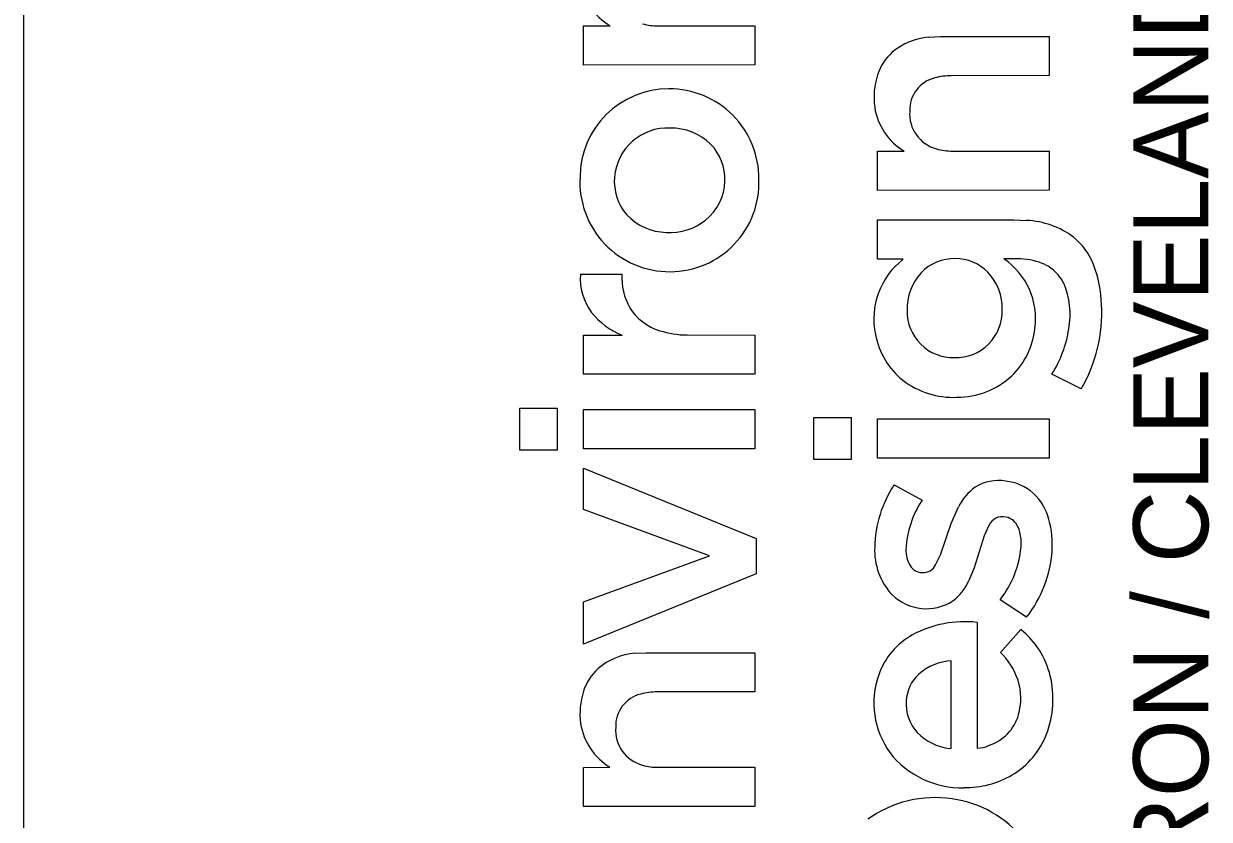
# Model space of a CAD drawing. Extents: x -0.2 to 34, y 0 to 22.
# Drawn here: x 32 to 32.901, y 2.778 to 3.382 of the extents above; entities that cross this region are included whole.
import ezdxf

# ---------------------------------------------------------------- set-up
doc = ezdxf.new("R2010")
doc.units = 0
doc.layers.add('SH_Border', color=7, linetype='Continuous')
doc.layers.add('SH_Cut_Line', color=7, linetype='Continuous')

msp = doc.modelspace()

# ---------------------------------------------------------------- linework, layer by layer
at = {"layer": 'SH_Border'}
for p, q in [((32.42542, 3.38066), (32.44552, 3.38071)), ((32.42542, 3.35086), (32.42542, 3.38066)), ((32.48222, 3.38071), (32.55569, 3.38071)), ((32.55569, 3.38071), (32.55571, 3.35096)), ((32.68784, 3.3722), (32.69634, 3.37266)), ((32.69634, 3.37266), (32.77916, 3.37266)), ((32.77916, 3.37266), (32.77917, 3.34287)), ((32.55571, 3.35096), (32.42542, 3.35086)), ((32.77917, 3.34287), (32.70485, 3.3428)), ((32.64888, 3.2855), (32.66897, 3.28555)), ((32.64888, 3.25569), (32.64888, 3.2855)), ((32.70568, 3.28555), (32.77915, 3.28555)), ((32.77915, 3.28555), (32.77917, 3.25579)), ((32.77917, 3.25579), (32.64888, 3.25569)), ((32.6489, 3.20336), (32.64889, 3.23322)), ((32.64889, 3.23322), (32.75236, 3.23322)), ((32.75236, 3.23322), (32.76191, 3.23285)), ((32.66836, 3.20336), (32.6489, 3.20336)), ((32.75763, 3.20356), (32.74487, 3.20361)), ((32.42299, 3.19193), (32.45454, 3.19193)), ((32.42542, 3.14577), (32.45473, 3.14579)), ((32.42542, 3.11593), (32.42542, 3.14577)), ((32.50413, 3.14581), (32.55571, 3.14573)), ((32.55571, 3.14573), (32.55565, 3.11593)), ((32.55565, 3.11593), (32.42542, 3.11593)), ((32.8036, 3.10491), (32.7812, 3.11598)), ((32.37705, 3.05818), (32.37705, 3.09026)), ((32.37705, 3.09026), (32.40543, 3.09026)), ((32.40543, 3.09026), (32.40543, 3.05818)), ((32.42542, 3.05942), (32.42542, 3.08928)), ((32.42542, 3.08928), (32.55571, 3.08928)), ((32.55571, 3.08928), (32.55571, 3.05942)), ((32.60051, 3.05111), (32.60051, 3.08319)), ((32.60051, 3.08319), (32.62889, 3.08319)), ((32.62889, 3.08319), (32.62889, 3.05111)), ((32.64888, 3.05234), (32.64888, 3.0822)), ((32.64888, 3.0822), (32.77917, 3.0822)), ((32.77917, 3.0822), (32.77917, 3.05234)), ((32.40543, 3.05818), (32.37705, 3.05818)), ((32.55571, 3.05942), (32.42542, 3.05942)), ((32.62889, 3.05111), (32.60051, 3.05111)), ((32.77917, 3.05234), (32.64888, 3.05234)), ((32.42542, 3.01327), (32.42542, 3.0446)), ((32.42542, 3.0446), (32.5567, 2.9913)), ((32.66151, 3.03207), (32.68268, 3.02025)), ((32.52117, 2.97798), (32.42542, 3.01327)), ((32.70483, 3.00258), (32.71036, 3.01526)), ((32.69675, 2.97868), (32.70483, 3.00258)), ((32.73342, 3.00101), (32.72985, 2.9933)), ((32.5567, 2.9913), (32.5567, 2.96441)), ((32.72985, 2.9933), (32.72213, 2.96882)), ((32.42542, 2.94294), (32.52117, 2.97798)), ((32.69299, 2.97117), (32.69675, 2.97868)), ((32.5567, 2.96441), (32.42542, 2.91086)), ((32.72213, 2.96882), (32.71822, 2.95921)), ((32.42542, 2.91086), (32.42542, 2.94294)), ((32.76214, 2.93141), (32.74198, 2.94469)), ((32.72453, 2.92747), (32.72463, 2.83195)), ((32.74228, 2.90465), (32.75768, 2.922)), ((32.46439, 2.90397), (32.47289, 2.90443)), ((32.47289, 2.90443), (32.55571, 2.90443)), ((32.55571, 2.90443), (32.55571, 2.87465)), ((32.70489, 2.83182), (32.70489, 2.89834)), ((32.55571, 2.87465), (32.4814, 2.87457)), ((32.70361, 2.83165), (32.70489, 2.83182)), ((32.42542, 2.81728), (32.44552, 2.81733)), ((32.42542, 2.78747), (32.42542, 2.81728)), ((32.48222, 2.81733), (32.55569, 2.81733)), ((32.55569, 2.81733), (32.55571, 2.78756)), ((32.55571, 2.78756), (32.42542, 2.78747))]:
    msp.add_line(p, q, dxfattribs=at)
for points in [[(32.42542, 3.35086), (32.42542, 3.38066), (32.44552, 3.38071)], [(32.48222, 3.38071), (32.55569, 3.38071), (32.55571, 3.35096), (32.42542, 3.35086)], [(32.68784, 3.3722), (32.69634, 3.37266), (32.77916, 3.37266), (32.77917, 3.34287), (32.70485, 3.3428)], [(32.64888, 3.25569), (32.64888, 3.2855), (32.66897, 3.28555)], [(32.70568, 3.28555), (32.77915, 3.28555), (32.77917, 3.25579), (32.64888, 3.25569)], [(32.66836, 3.20336), (32.6489, 3.20336), (32.64889, 3.23322), (32.75236, 3.23322), (32.76191, 3.23285)], [(32.75763, 3.20356), (32.74487, 3.20361)], [(32.42299, 3.19193), (32.45454, 3.19193)], [(32.50413, 3.14581), (32.55571, 3.14573), (32.55565, 3.11593), (32.42542, 3.11593)], [(32.42542, 3.11593), (32.42542, 3.14577), (32.45473, 3.14579)], [(32.8036, 3.10491), (32.7812, 3.11598)], [(32.66151, 3.03207), (32.68268, 3.02025)], [(32.69299, 2.97117), (32.69675, 2.97868), (32.70483, 3.00258), (32.71036, 3.01526)], [(32.73342, 3.00101), (32.72985, 2.9933), (32.72213, 2.96882), (32.71822, 2.95921)], [(32.76214, 2.93141), (32.74198, 2.94469)], [(32.72453, 2.92747), (32.72463, 2.83195)], [(32.74228, 2.90465), (32.75768, 2.922)], [(32.46439, 2.90397), (32.47289, 2.90443), (32.55571, 2.90443), (32.55571, 2.87465), (32.4814, 2.87457)], [(32.70361, 2.83165), (32.70489, 2.83182), (32.70489, 2.89834)], [(32.42542, 2.78747), (32.42542, 2.81728), (32.44552, 2.81733)], [(32.48222, 2.81733), (32.55569, 2.81733), (32.55571, 2.78756), (32.42542, 2.78747)]]:
    msp.add_lwpolyline(points, dxfattribs=at)
for points in [[(32.37705, 3.05818), (32.37705, 3.09026), (32.40543, 3.09026), (32.40543, 3.05818)], [(32.42542, 3.05942), (32.42542, 3.08928), (32.55571, 3.08928), (32.55571, 3.05942)], [(32.60051, 3.05111), (32.60051, 3.08319), (32.62889, 3.08319), (32.62889, 3.05111)], [(32.64888, 3.05234), (32.64888, 3.0822), (32.77917, 3.0822), (32.77917, 3.05234)], [(32.42542, 2.91086), (32.42542, 2.94294), (32.52117, 2.97798), (32.42542, 3.01327), (32.42542, 3.0446), (32.5567, 2.9913), (32.5567, 2.96441)]]:
    msp.add_lwpolyline(points, close=True, dxfattribs=at)
for centre, radius, start, end in [((32.47027, 3.42141), 0.04763, 188.96462, 238.69865), ((32.47027, 3.42141), 0.04763, 188.96462, 238.69865), ((32.48183, 3.42286), 0.04215, 254.08913, 270.52838), ((32.48183, 3.42286), 0.04215, 254.08913, 270.52838), ((32.69216, 3.32251), 0.04988, 94.97056, 130.22484), ((32.69216, 3.32251), 0.04988, 94.97056, 130.22484), ((32.68694, 3.33085), 0.04016, 132.22383, 161.68229), ((32.68694, 3.33085), 0.04016, 132.22383, 161.68229), ((32.70217, 3.32642), 0.05602, 162.27398, 187.79173), ((32.70217, 3.32642), 0.05602, 162.27398, 187.79173), ((32.70453, 3.29679), 0.04601, 89.60515, 105.33026), ((32.70453, 3.29679), 0.04601, 89.60515, 105.33026), ((32.69828, 3.31689), 0.02498, 103.68683, 182.21395), ((32.69828, 3.31689), 0.02498, 103.68683, 182.21395), ((32.49014, 3.26543), 0.0674, 89.84756, 179.64047), ((32.49014, 3.26543), 0.0674, 89.84756, 179.64047), ((32.49057, 3.26474), 0.0681, 359.54009, 90.21138), ((32.49057, 3.26474), 0.0681, 359.54009, 90.21138), ((32.69372, 3.32624), 0.04763, 188.96462, 238.69865), ((32.69372, 3.32624), 0.04763, 188.96462, 238.69865), ((32.7008, 3.31381), 0.02757, 175.58441, 255.13816), ((32.7008, 3.31381), 0.02757, 175.58441, 255.13816), ((32.48923, 3.26263), 0.0404, 87.04809, 175.57259), ((32.48923, 3.26263), 0.0404, 87.04809, 175.57259), ((32.49204, 3.25999), 0.04299, 45.84264, 90.98008), ((32.49204, 3.25999), 0.04299, 45.84264, 90.98008), ((32.49458, 3.26421), 0.03821, 357.88569, 44.15902), ((32.49458, 3.26421), 0.03821, 357.88569, 44.15902), ((32.70529, 3.32769), 0.04215, 254.08913, 270.52838), ((32.70529, 3.32769), 0.04215, 254.08913, 270.52838), ((32.49083, 3.26209), 0.06819, 176.8344, 270.40384), ((32.49083, 3.26209), 0.06819, 176.8344, 270.40384), ((32.48729, 3.2625), 0.03848, 175.15378, 221.14706), ((32.48729, 3.2625), 0.03848, 175.15378, 221.14706), ((32.49123, 3.26139), 0.06749, 270.06243, 2.37759), ((32.49123, 3.26139), 0.06749, 270.06243, 2.37759), ((32.49446, 3.26318), 0.0383, 308.28936, 359.43468), ((32.49446, 3.26318), 0.0383, 308.28936, 359.43468), ((32.48919, 3.26607), 0.04228, 223.09994, 268.80895), ((32.48919, 3.26607), 0.04228, 223.09994, 268.80895), ((32.49096, 3.2679), 0.04418, 266.56515, 308.06078), ((32.49096, 3.2679), 0.04418, 266.56515, 308.06078), ((32.75907, 3.16789), 0.06503, 53.40344, 87.49062), ((32.75907, 3.16789), 0.06503, 53.40344, 87.49062), ((32.76517, 3.18039), 0.05141, 21.60748, 50.5577), ((32.76517, 3.18039), 0.05141, 21.60748, 50.5577), ((32.70292, 3.15813), 0.05692, 127.37482, 192.22468), ((32.70292, 3.15813), 0.05692, 127.37482, 192.22468), ((32.70693, 3.16927), 0.0346, 88.47302, 136.42562), ((32.70693, 3.16927), 0.0346, 88.47302, 136.42562), ((32.70814, 3.16963), 0.03424, 44.27195, 90.47623), ((32.70814, 3.16963), 0.03424, 44.27195, 90.47623), ((32.71421, 3.15829), 0.05472, 352.1125, 55.92295), ((32.71421, 3.15829), 0.05472, 352.1125, 55.92295), ((32.75666, 3.15725), 0.04633, 65.01687, 88.8011), ((32.75666, 3.15725), 0.04633, 65.01687, 88.8011), ((32.7626, 3.17155), 0.03085, 26.26808, 63.80301), ((32.7626, 3.17155), 0.03085, 26.26808, 63.80301), ((32.73069, 3.16714), 0.08835, 1.15143, 21.3627), ((32.73069, 3.16714), 0.08835, 1.15143, 21.3627), ((32.46616, 3.18882), 0.04329, 175.87313, 216.34747), ((32.46616, 3.18882), 0.04329, 175.87313, 216.34747), ((32.50087, 3.18948), 0.04639, 176.9688, 209.60636), ((32.50087, 3.18948), 0.04639, 176.9688, 209.60636), ((32.71141, 3.16602), 0.0401, 137.46739, 182.33237), ((32.71141, 3.16602), 0.0401, 137.46739, 182.33237), ((32.70368, 3.166), 0.03996, 358.57141, 43.53765), ((32.70368, 3.166), 0.03996, 358.57141, 43.53765), ((32.73565, 3.16154), 0.05953, 349.30734, 23.43071), ((32.73565, 3.16154), 0.05953, 349.30734, 23.43071), ((32.47466, 3.19716), 0.05511, 218.09809, 248.7907), ((32.47466, 3.19716), 0.05511, 218.09809, 248.7907), ((32.49514, 3.18814), 0.04079, 211.94466, 253.2028), ((32.49514, 3.18814), 0.04079, 211.94466, 253.2028), ((32.70645, 3.1637), 0.03511, 178.88208, 271.08374), ((32.70645, 3.1637), 0.03511, 178.88208, 271.08374), ((32.70818, 3.16404), 0.03546, 268.27882, 1.55016), ((32.70818, 3.16404), 0.03546, 268.27882, 1.55016), ((32.70538, 3.16244), 0.11383, 329.6388, 3.25998), ((32.70538, 3.16244), 0.11383, 329.6388, 3.25998), ((32.50465, 3.2165), 0.07069, 252.46555, 269.57296), ((32.50465, 3.2165), 0.07069, 252.46555, 269.57296), ((32.70463, 3.15696), 0.05837, 190.75182, 231.28919), ((32.70463, 3.15696), 0.05837, 190.75182, 231.28919), ((32.70988, 3.15708), 0.05887, 313.74196, 353.8554), ((32.70988, 3.15708), 0.05887, 313.74196, 353.8554), ((32.70738, 3.16334), 0.08771, 327.31495, 351.57478), ((32.70738, 3.16334), 0.08771, 327.31495, 351.57478), ((32.70632, 3.16112), 0.06269, 232.46061, 272.59022), ((32.70632, 3.16112), 0.06269, 232.46061, 272.59022), ((32.70954, 3.15901), 0.06051, 269.6361, 312.70877), ((32.70954, 3.15901), 0.06051, 269.6361, 312.70877), ((32.73636, 2.98258), 0.08973, 146.53104, 178.7571), ((32.73636, 2.98258), 0.08973, 146.53104, 178.7571), ((32.74661, 2.99713), 0.04053, 125.51182, 153.41595), ((32.74661, 2.99713), 0.04053, 125.51182, 153.41595), ((32.7406, 3.0026), 0.03263, 80.17192, 122.51969), ((32.7406, 3.0026), 0.03263, 80.17192, 122.51969), ((32.74278, 2.99824), 0.03667, 47.79344, 84.68918), ((32.74278, 2.99824), 0.03667, 47.79344, 84.68918), ((32.74519, 2.9789), 0.07495, 146.51121, 176.91007), ((32.74519, 2.9789), 0.07495, 146.51121, 176.91007), ((32.73788, 2.9946), 0.04267, 14.9966, 46.20632), ((32.73788, 2.9946), 0.04267, 14.9966, 46.20632), ((32.74384, 2.99631), 0.01143, 76.66094, 155.7053), ((32.74384, 2.99631), 0.01143, 76.66094, 155.7053), ((32.74397, 2.99511), 0.01256, 21.5098, 78.52618), ((32.74397, 2.99511), 0.01256, 21.5098, 78.52618), ((32.71044, 2.98674), 0.07121, 355.83062, 15.39138), ((32.71044, 2.98674), 0.07121, 355.83062, 15.39138), ((32.72592, 2.98766), 0.03209, 354.57264, 22.06805), ((32.72592, 2.98766), 0.03209, 354.57264, 22.06805), ((32.69666, 2.98238), 0.05005, 177.53659, 222.79318), ((32.69666, 2.98238), 0.05005, 177.53659, 222.79318), ((32.6931, 2.98233), 0.02276, 178.47474, 211.08679), ((32.6931, 2.98233), 0.02276, 178.47474, 211.08679), ((32.68248, 2.99149), 0.0757, 321.81101, 354.79685), ((32.68248, 2.99149), 0.0757, 321.81101, 354.79685), ((32.68952, 2.9882), 0.09219, 321.9777, 355.87384), ((32.68952, 2.9882), 0.09219, 321.9777, 355.87384), ((32.68331, 2.9767), 0.01148, 212.23676, 268.37769), ((32.68331, 2.9767), 0.01148, 212.23676, 268.37769), ((32.68342, 2.97589), 0.01067, 267.71603, 333.73375), ((32.68342, 2.97589), 0.01067, 267.71603, 333.73375), ((32.68098, 2.9758), 0.04077, 308.08772, 335.98736), ((32.68098, 2.9758), 0.04077, 308.08772, 335.98736), ((32.68599, 2.97535), 0.0375, 225.98539, 302.47965), ((32.68599, 2.97535), 0.0375, 225.98539, 302.47965), ((32.7152, 2.84414), 0.08384, 83.61499, 118.28755), ((32.7152, 2.84414), 0.08384, 83.61499, 118.28755), ((32.71744, 2.87167), 0.06443, 13.53365, 51.36148), ((32.71744, 2.87167), 0.06443, 13.53365, 51.36148), ((32.70239, 2.86906), 0.05583, 118.83082, 160.62438), ((32.70239, 2.86906), 0.05583, 118.83082, 160.62438), ((32.46871, 2.85428), 0.04988, 94.96958, 130.22249), ((32.46871, 2.85428), 0.04988, 94.96958, 130.22249), ((32.70378, 2.86556), 0.05486, 19.03571, 45.44059), ((32.70378, 2.86556), 0.05486, 19.03571, 45.44059), ((32.46348, 2.86263), 0.04015, 132.22192, 161.68183), ((32.46348, 2.86263), 0.04015, 132.22192, 161.68183), ((32.70785, 2.85609), 0.04235, 94.00805, 130.88169), ((32.70785, 2.85609), 0.04235, 94.00805, 130.88169), ((32.71041, 2.86612), 0.06437, 160.52012, 215.78311), ((32.71041, 2.86612), 0.06437, 160.52012, 215.78311), ((32.70048, 2.86628), 0.02985, 132.98507, 177.179), ((32.70048, 2.86628), 0.02985, 132.98507, 177.179), ((32.71069, 2.8697), 0.047, 344.60586, 17.007), ((32.71069, 2.8697), 0.047, 344.60586, 17.007), ((32.70635, 2.86921), 0.07579, 339.3542, 13.37853), ((32.70635, 2.86921), 0.07579, 339.3542, 13.37853), ((32.47872, 2.85819), 0.05601, 162.27355, 187.79185), ((32.47872, 2.85819), 0.05601, 162.27355, 187.79185), ((32.48108, 2.82856), 0.04601, 89.60494, 105.3284), ((32.48108, 2.82856), 0.04601, 89.60494, 105.3284), ((32.47482, 2.84867), 0.02498, 103.68646, 182.21874), ((32.47482, 2.84867), 0.02498, 103.68646, 182.21874), ((32.7017, 2.86503), 0.03115, 175.00126, 223.28301), ((32.7017, 2.86503), 0.03115, 175.00126, 223.28301), ((32.7224, 2.86715), 0.03504, 288.00773, 343.55078), ((32.7224, 2.86715), 0.03504, 288.00773, 343.55078), ((32.47026, 2.85802), 0.04762, 188.96199, 238.70369), ((32.47026, 2.85802), 0.04762, 188.96199, 238.70369), ((32.47735, 2.84558), 0.02756, 175.58538, 255.14386), ((32.47735, 2.84558), 0.02756, 175.58538, 255.14386), ((32.70891, 2.87363), 0.04231, 225.06188, 262.79738), ((32.70891, 2.87363), 0.04231, 225.06188, 262.79738), ((32.71894, 2.8652), 0.0626, 300.94269, 338.73225), ((32.71894, 2.8652), 0.0626, 300.94269, 338.73225), ((32.72474, 2.85216), 0.02021, 269.7003, 294.8711), ((32.72474, 2.85216), 0.02021, 269.7003, 294.8711), ((32.71253, 2.87054), 0.06872, 217.74516, 271.65431), ((32.71253, 2.87054), 0.06872, 217.74516, 271.65431), ((32.48183, 2.85948), 0.04215, 254.09162, 270.52835), ((32.48183, 2.85948), 0.04215, 254.09162, 270.52835), ((32.71549, 2.87241), 0.07056, 269.20477, 300.33412), ((32.71549, 2.87241), 0.07056, 269.20477, 300.33412), ((32.69229, 2.70792), 0.08641, 81.19402, 125.99844), ((32.69229, 2.70792), 0.08641, 81.19402, 125.99844), ((32.69458, 2.71132), 0.08272, 37.85208, 82.40204), ((32.69458, 2.71132), 0.08272, 37.85208, 82.40204)]:
    msp.add_arc(centre, radius, start, end, dxfattribs=at)
at = {"layer": 'SH_Cut_Line'}
msp.add_line((32, 0.5), (32, 21.5), dxfattribs=at)

# ---------------------------------------------------------------- texts
at = {"layer": 'SH_Border'}
msp.add_text('AKRON / CLEVELAND / COLUMBUS', height=0.056969, rotation=90, dxfattribs=at).set_placement((32.90012, 2.638))

doc.saveas('drawing.dxf')
